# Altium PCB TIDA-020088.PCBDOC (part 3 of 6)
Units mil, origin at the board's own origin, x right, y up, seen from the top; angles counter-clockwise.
Board outline 7520.69 x 5119.11 mil, 6 copper layers (TOP, GND02, SIG03, SIG04, GND05, BOTTOM), stack 87.024 mil thick; 539 components, 269 nets, 1479 pads, 2085 vias.
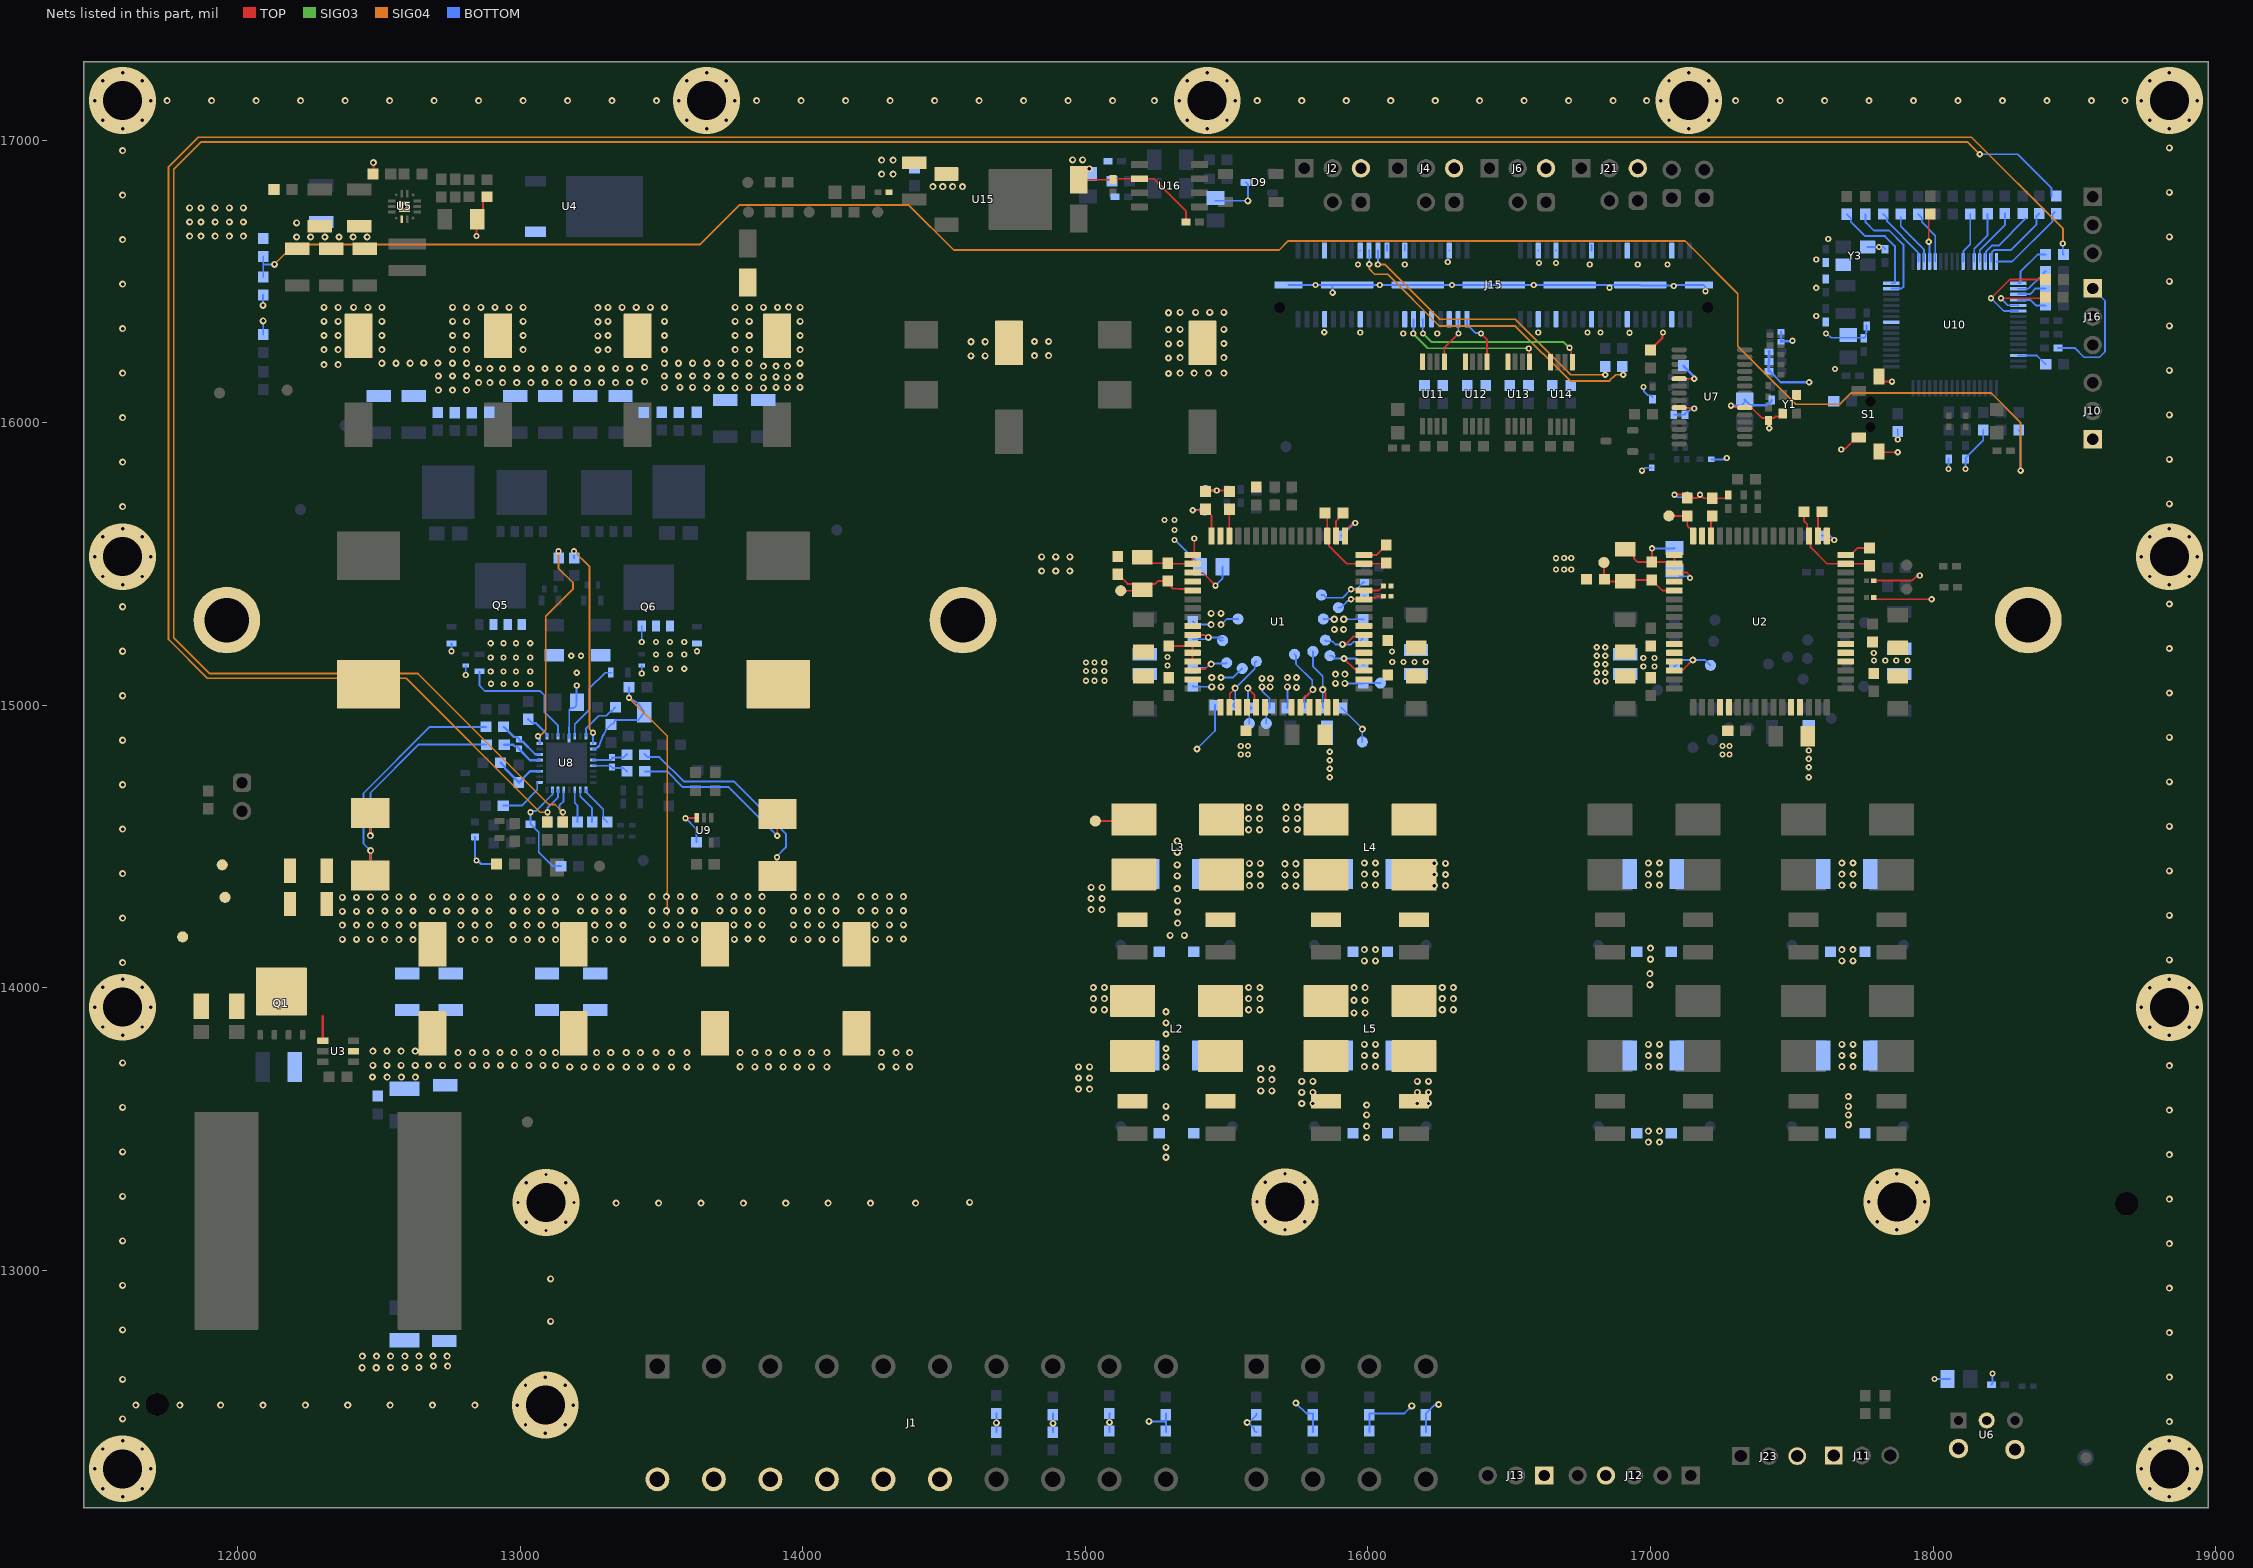
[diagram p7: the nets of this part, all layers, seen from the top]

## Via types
v1: diameter 25, hole 12, TOP to BOTTOM, tented both sides, 1621 vias
v2: diameter 22, hole 10, TOP to BOTTOM, tented both sides, 436 vias
v3: diameter 236.22, hole 137.8, TOP to BOTTOM, 15 vias
v4: diameter 19.68, hole 7.87, TOP to BOTTOM, tented both sides, 12 vias
v5: diameter 19.68, hole 7.87, TOP to BOTTOM, 1 vias

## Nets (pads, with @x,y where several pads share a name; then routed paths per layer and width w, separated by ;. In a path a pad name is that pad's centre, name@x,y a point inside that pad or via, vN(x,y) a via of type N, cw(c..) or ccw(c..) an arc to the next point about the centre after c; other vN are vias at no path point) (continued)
BIAS: C115.1 C116.1 C117.1 C118.1 C155.1 C156.1 C157.1 C158.1 C159.1 C160.1 C182.2 C183.1 D1.1 D2.1 L1.1 L6.1 L11.1 L13.1 L21.1 Q1.5 Q1.6 Q1.7 Q1.8 Q1.9@12154.41,13986.97 R62.1 R77.2 R78.1 R88.2 R89.2 R94.1 TP60.1 U3.4 U8.18 | length 2986.9
  TOP w6.5: R77.2@12469.31,14397.51 12470,14398.2 v1(12470,14485) ; v2(13908,14461.62) 13908,14396.76 R78.1@13910,14394.76
  TOP w8: 12300,13900 12300.87,13899.13 U3.4@12300.87,13812.4
  SIG04 w6.5: v2(13384.49,15026.46) 13520,14890.95 13520,14335.68 13519.44,14335.12 13519.44,14322.88 13520,14322.32 13519.44,14321.76 13519.44,14309.52 13520,14308.96 13520,14279.8 13519.44,14279.25 13519.44,14272.88 13520,14272.32 13520,14257.51
  BOTTOM w6.5: 12450,14400.42 12465,14415.42 ; v1(12470,14485) 12445,14510 12445,14688.33 12679.68,14923.01 R88.2@12878.05,14923.01 ; U8.18@13264.38,14844.84 U8.18@13257.65,14844.84 13265.46,14845.76 13273.95,14850.91 ; 13279.14,14857.14 13292.42,14891.84 ; 13293.17,14893.39 13306.23,14915.71 R94.1@13320.93,14931.4 13329.91,14934.97 13335.63,14947.08 13416.59,14947.08 C182.2@13438.18,14975.1 13416.59,15007.51 v2(13384.49,15026.46) 13384.49,15048.08 C183.1@13385.21,15062.78 ; R89.2@13439.99,14827.01 13450.78,14816.21 13492.12,14816.21 13578.33,14730 13755,14730 13940,14545 13940,14496.39 13908,14464.39 v2(13908,14461.62)
  BOTTOM w8: 12470,14450 v1(12470,14485) ; 13273.95,14850.91 ccw(c13267.49,14861.57) 13279.14,14857.14 ; 13292.42,14891.84 cw(c13302.23,14888.09) 13293.17,14893.39 ; 13908,14429.19 v2(13908,14461.62)
  other v1: 12520,14170 12570,14170 12620,14170 12790,14170 12840,14170 12890,14170 12975,14170 13025,14170 13075,14170 13125,14170 13265,14170 12370.31,14171.36 12420.31,14171.36 12470.31,14171.36 13313.42,14171.36 13363.42,14171.36 13467.52,14170.96 13517.52,14170.96 13567.52,14170.96 13617.52,14170.96 13757.52,14170.96 13967.52,14170.96 14017.52,14170.96 14067.52,14170.96 14117.52,14170.96 14257.52,14170.96 13805.94,14172.32 13855.94,14172.32 14305.94,14172.32 14355.94,14172.32 12370.31,14221.36 12420.31,14221.36 12470.31,14221.36 12520.31,14221.36 12570.31,14221.36 12620.31,14221.36 12789.68,14221.36 12839.68,14221.36 12889.68,14221.36 12974.05,14221.36 13024.05,14221.36 13074.05,14221.36 13124.05,14221.36 13263.42,14221.36 13313.42,14221.36 13363.42,14221.36 13466.57,14222.32 13516.57,14222.32 13566.57,14222.32 13616.57,14222.32 13755.94,14222.32 13805.94,14222.32 13855.94,14222.32 13966.57,14222.32 14016.57,14222.32 14066.57,14222.32 14116.57,14222.32 14255.94,14222.32 14305.94,14222.32 14355.94,14222.32 12370,14270 12420,14270 12470.31,14271.36 12520.31,14271.36 12570.31,14271.36 12620.31,14271.36 12689.68,14271.36 12739.68,14271.36 12789.68,14271.36 12839.68,14271.36 12889.68,14271.36 12974.05,14271.36 13024.05,14271.36 13074.05,14271.36 13124.05,14271.36 13213.42,14271.36 13263.42,14271.36 13313.42,14271.36 13363.42,14271.36 13466.57,14272.32 13516.57,14272.32 13566.57,14272.32 13616.57,14272.32 13705.94,14272.32 13755.94,14272.32 13805.94,14272.32 13855.94,14272.32 13966.57,14272.32 14016.57,14272.32 14066.57,14272.32 14116.57,14272.32 14205.94,14272.32 14255.94,14272.32 14305.94,14272.32 14355.94,14272.32 12370,14320 12420,14320 12470.31,14321.36 12520.31,14321.36 12570.31,14321.36 12620.31,14321.36 12689.68,14321.36 12739.68,14321.36 12789.68,14321.36 12839.68,14321.36 12889.68,14321.36 12974.05,14321.36 13024.05,14321.36 13074.05,14321.36 13124.05,14321.36 13213.42,14321.36 13263.42,14321.36 13313.42,14321.36 13363.42,14321.36 13466.57,14322.32 13516.57,14322.32 13566.57,14322.32 13616.57,14322.32 13705.94,14322.32 13755.94,14322.32 13805.94,14322.32 13855.94,14322.32 13966.57,14322.32 14016.57,14322.32 14066.57,14322.32 14116.57,14322.32 14205.94,14322.32 14255.94,14322.32 14305.94,14322.32 14355.94,14322.32 14845,15475 14895,15475 14945,15475 14845,15525 14895,15525 14945,15525 11829.5,16660 11870,16660 11920,16660 11970,16660 12020,16660 11829.5,16710 11870,16710 11920,16710 11970,16710 12020,16710 11829.5,16760 11870,16760 11920,16760 11970,16760 12020,16760 14278.8,16879.14 14319.3,16879.14 14278.8,16929.14 14319.3,16929.14
  other v2: 16665,15480.63 16694.37,15480.63 16719.37,15480.63 16665,15520 16694.37,15520.63 16719.37,15520.63
CAN_RX: R79.2 U10.6 | length 335.9
  TOP w6.5: v2(18205,16440) 18271.46,16506.46 R79.2@18398.5,16506.46
  BOTTOM w6.5: v2(18205,16440) 18250.01,16394.99 U10.6@18301.19,16394.99
CAN_STB: R71.2 U10.52 | length 171.6
  TOP w6.5: v2(17985,16640) 17985,16733.44 R71.2@17989.63,16738.08 R71.2@17990,16737.71
  BOTTOM w6.5: v2(17985,16640) 17987.29,16637.71 17987.29,16571.09 U10.52@17988.2,16570.19
CAN_TX: R70.2 U10.5 | length 230.7
  TOP w6.5: v2(18240,16440) 18393.26,16440 R70.2@18397.31,16444.05
  BOTTOM w6.5: v2(18240,16440) 18264.42,16415.58 18300.28,16415.58 U10.5@18301.19,16414.68
CFG0: R110.1 U8.27 | length 111.8
  BOTTOM w6.5: U8.27@13192.69,14694.33 13192.69,14653.94 13202.26,14644.37 R110.1@13202.26,14586.5
CFG1: R107.2 U8.26 | length 132
  BOTTOM w6.5: U8.26@13212.37,14701.14 13212.37,14677.63 13254.26,14635.74 R107.2@13254.26,14586.5
CFG2: R103.1 U8.25 | length 145.8
  BOTTOM w6.5: U8.25@13232.06,14701.14 13232.06,14692.94 13293.56,14631.44 13293.56,14600.2 R103.1@13307.26,14586.5
COMP: C191.1 C192.1 U8.3 | length 187.5
  BOTTOM w8: C192.1@12930.41,14796 12931.4,14796 12946.1,14781.3 12946.1,14775.71 C191.1@12995.11,14726.69 ; C191.1@12995.11,14725.71 C191.1@12995.11,14726.69 ; U8.3@13068.67,14766.1 13034.52,14766.1 C191.1@12995.11,14726.69
CSN1: C177.2 R87.1 U8.5 | length 149.2
  BOTTOM w8: R87.1@12943.17,14860.31 12974.86,14860.31 12981.5,14853.66 12987.84,14853.66 12995.11,14846.4 C177.2@12995.11,14845.55 12995.11,14844.71 13034.35,14805.47 U8.5@13068.67,14805.47
CSN2: C178.2 R90.1 U8.21 | length 128.6
  BOTTOM w6.5: U8.21@13257.65,14785.79 13313.5,14785.79 13314.68,14784.61 13319.36,14784.61 13325.63,14778.34 13325.63,14777.5 13365.16,14777.5 R90.1@13377.27,14765.39
CSP1: C177.1 R88.1 U8.6 | length 169.1
  BOTTOM w8: R88.1@12941.04,14923.01 12942.03,14923.01 12977.63,14887.41 12987.84,14887.41 12995.11,14880.14 C177.1@12995.11,14879.3 12995.11,14878.45 13002.38,14871.18 13007.71,14871.18 13052.93,14825.97 13067.86,14825.97 U8.6@13068.67,14825.16
CSP2: C178.1 R89.1 U8.20 | length 128.1
  BOTTOM w6.5: U8.20@13257.65,14805.47 13257.73,14805.55 13319.94,14805.55 C178.1@13325.63,14811.24 ; C178.1@13324.43,14814.58 13364.56,14814.58 R89.1@13376.99,14827.01
DLY: C194.1 U8.1 | length 171.1
  BOTTOM w6.5: C194.1@12939.61,14644.37 13004.37,14644.37 13060.11,14700.11 13060.11,14725.06 13061.78,14726.73 U8.1@13061.94,14726.73
EN2: R97.2 R101.1 R145.2 U8.30 | length 10407.7
  TOP w6.5: R101.1@13095.63,14586.5 13096.39,14587.26 v2(13096.39,14620.98)
  SIG04 w6.5: v2(13096.39,14620.98) 13069.67,14620.98 12595.66,15095 11892.37,15095 11755,15232.37 11755,16905 11860,17010 18136.11,17010 18460,16686.11 18460,16635 v2(18458.94,16633.94)
  BOTTOM w6.5: R97.2@13095.63,14586.5 13096.39,14587.26 v2(13096.39,14620.98) 13096.72,14621.31 13096.72,14637.42 13133.63,14674.33 U8.30@13133.63,14701.14 ; v2(18458.94,16633.94) 18458.94,16597.55 R145.2@18461.5,16595
GND: C1.1 C2.2 C3.1 C4.1 C6.2 C7.2 C8.2 C9.1 C10.2 C11.2 C13.2 C14.2 C15.2 C16.2 C17.2 C18.2 C20.2 C21.2 C23.2 C24.2 C25.2 C26.2 C27.2 C28.2 C31.2 C32.2 C33.2 C34.2 C35.2 C36.2 C39.2 C40.2 C41.2 C42.2 C43.2 C44.2 C47.2 C48.2 C49.2 C50.2 C51.2 C52.2 C53.1 C54.2 C55.1 C56.1 C58.2 C59.2 C60.2 C61.1 C62.2 C63.2 C65.2 C66.2 C67.2 C68.2 C69.2 C70.2 C72.2 C73.2 C75.2 C76.2 C77.2 C78.2 C79.2 C80.2 C83.2 C84.2 C85.2 C86.2 C87.2 C88.2 C91.2 C92.2 C93.2 C94.2 C95.2 C96.2 C99.2 C100.2 C101.2 C102.2 C103.2 C104.2 C106.2 C107.2 C108.2 C109.2 C110.2 C111.2 C112.2 C113.2 C114.2 C115.2 C116.2 C117.2 C118.2 C120.2 C121.2 C122.2 C123.2 C124.2 C125.2 C126.2 C127.2 C128.2 C129.2 C130.2 C131.2 C132.2 C133.2 C134.1 C135.1 C136.2 C137.2 C138.2 C139.2 C140.1 C141.2 C142.2 C143.1 C144.2 C145.2 C146.2 C147.2 C148.2 C149.2 C150.2 C151.2 C152.2 C153.2 C154.1 C155.2 C156.2 C157.2 C158.2 C159.2 C160.2 C161.2 C162.2 C163.2 C164.2 C165.2 C166.2 C167.2 C168.2 C169.2 C170.2 C171.2 C172.2 C173.2 C174.2 C187.1 C188.1 C189.2 C193.2 C196.1 C197.1 C198.1 C199.1 C200.2 C201.2 C202.1 C203.2 C204.2 C206.1 C207.1 C208.1 C209.1 C210.1 C211.1 C212.1 C213.1 C214.1 C215.1 C216.2 C217.2 C218.2 C219.2 C220.2 C221.2 C222.2 C223.2 C224.2 C225.2 D9.3 J1.2 J1.4 J1.6 J1.8 J1.10 J1.12 J2.3 J4.3 J6.3 J10.1 J11.1 J12.4 J13.1 J15.7 J15.8 J15.15 J15.16 J15.22 J15.25 J15.26 J15.31 J15.35 J15.36 J15.45 J15.46 J15.49 J15.50 J15.57 J15.58 J15.65 J15.66 J15.75 J15.76 J15.P1 J15.P2 J16.1 J21.3 J23.3 NT1.2 pad.1@11961.37,15301.37 pad.1@14566.37,15301.37 pad.1@18336.64,15301.37 Q5.1 Q5.2 Q5.3 Q6.1 Q6.2 Q6.3 R19.2 R34.2 R36.2 R39.1 R41.1 R51.2 R54.2 R55.2 R57.1 R58.2 R63.2 R86.1 R91.1 R92.1 R93.1 R112.1 R121.2 R126.1 RT3.1 RT4.1 S1.1 S1.2 S1.3 TP2.1 TP30.1 TP76.1 TP77.1 U1.1 U1.15 U1.17 U1.18 U1.20 U1.27 U1.28 U1.29 U1.36 U1.37 U1.44 U1.45 U1.52 U1.53 U1.54 U2.1 U2.15 U2.17 U2.18 U2.20 U2.27 U2.28 U2.29 U2.36 U2.37 U2.44 U2.45 U2.52 U2.53 U2.54 U3.2 U4.1 U5.6 U5.15 U6.2 U6.4 U6.5 U7.6 U7.19 U7.23 U8.13 U9.3 U10.41 U11.4 U12.4 U13.4 U14.4 U15.1 U16.2 Y1.2 Y1.4 Y3.2 Y3.4 | length 8494
  TOP w6.5: R41.1@12478.5,16880 12480,16881.5 v1(12480,16920) ; v2(12845,16660) 12845,16717.91 C122.2@12847.09,16720 12867.68,16740.59 12867.68,16786.3 12881.38,16800 R36.2@12881.5,16800 12882.48,16800 12896.18,16786.3 R36.2@12896.18,16785.31 ; v2(13585,14600) 13585.91,14600.91 13623.5,14600.91 U9.3@13624.41,14601.81 ; C114.2@14976.56,16859.82 15097.31,16859.82 C172.2@15097.35,16859.86 15100.84,16863.35 U16.2@15191.58,16863.35 15241.65,16863.35 15356.38,16748.62 C171.2@15356.38,16710 ; C13.2@15200.63,15522.71 15221.2,15502.14 C14.2@15290.63,15502.14 15292.41,15500.35 U1.18@15379.37,15500.35 U1.17@15379.37,15531.85 15385,15537.48 v2(15385,15590) ; C3.1@15295.63,15209.14 15352.92,15209.14 15360.67,15216.89 U1.27@15379.37,15216.89 U1.28@15379.37,15185.39 U1.29@15379.37,15153.9 ; C1.1@15425,15756.5 15428.5,15760 v2(15465,15760) 15506.5,15760 C9.1@15510,15756.5 ; U1.1@15918.74,15598.78 15918.74,15617.48 15943.96,15642.7 15952.7,15642.7 v2(15955,15645) ; C65.2@16923.47,15565.56 C65.2@16910,15552.09 16920.83,15552.09 16941.42,15531.5 16941.42,15520.67 16955.59,15506.5 C66.2@17005,15506.5 17059.53,15506.5 17065.67,15500.35 U2.18@17084.37,15500.35 U2.17@17084.37,15531.85 ; v2(17085,15745) 17117.99,15745 C53.1@17130,15732.99 17162.99,15732.99 v2(17175,15745) 17187.63,15732.37 C61.1@17218.97,15732.37 17263.75,15732.37 17264.25,15732.87 17268.19,15732.87 17275,15739.68 R34.2@17275,15743.62 ; U7.23@17101.14,16052.98 17102.61,16051.51 17153.49,16051.51 v2(17155,16050) ; U7.19@17101.14,16155.35 17154.65,16155.35 v2(17155,16155) ; v2(17285,16060) 17288.25,16060 17293.79,16054.46 U7.6@17333.42,16054.46 ; U7.6@17333.42,16052.98 17354.21,16052.98 17358.07,16049.13 17360.87,16049.13 17393.53,16016.47 17437.76,16016.47 17443.33,16022.03 17457.82,16022.03 Y1.2@17467.91,16032.13 ; U2.1@17623.74,15598.78 17623.74,15592.58 17631.32,15585 v2(17650,15585) ; v2(17675,15905) 17677.3,15907.3 17689.54,15907.3 17729.57,15947.32 S1.3@17737.44,15947.32 ; C72.2@17790,15380.94 17790.79,15380.94 17796.72,15375 v2(17995,15375) ; C73.2@17790,15440 17791.32,15441.32 17926.32,15441.32 17941.7,15456.7 17950.65,15456.7 v2(17952.95,15459) ; S1.1@17808.31,15897.13 17810.43,15895 v2(17875,15895) ; S1.2@17808.31,16162.87 17808.31,16159.69 17822.99,16145 v2(17855,16145)
  TOP w8: C137.2@17000,16256.5 17000,16257.48 17041.07,16298.55 17041.07,16315.92 v2(17043.75,16318.6) ; C66.2@17005,15506.5 v2(17005,15555) ; C128.2@17417.28,16007.75 17418.64,16006.39 17418.64,15981.36 v2(17420,15980)
  BOTTOM w6.5: v1(12089.18,16415.09) 12089.18,16451.18 R63.2@12090,16452.01 ; R51.2@12090,16311.5 v1(12090,16360) ; v2(12756.5,15191) RT3.1@12756.5,15218 ; v2(12806.83,15107.23) R92.1@12806.83,15140 ; NT1.2@13172.59,14882.69 13172.59,14922.4 13173.11,14922.4 13173.11,14983.55 13178.97,14989.41 13189.25,14989.41 13198.03,14998.19 13198.03,15010 13199.02,15010.98 13199.02,15069.02 v2(13200,15070) ; v2(13430,15112) R93.1@13430,15140 ; v2(13430,15223.86) Q6.3@13430,15279.96 ; v2(13585,14600) 13623.5,14561.5 C193.2@13623.5,14515 ; C27.2@14685,12426.57 v1(14685,12460) C28.2@14685,12493.43 ; C35.2@14885,12426.57 14885.4,12426.98 14885.4,12493.02 C36.2@14885,12493.43 ; C43.2@15085,12426.57 15085.07,12426.64 15085.07,12493.36 C44.2@15085,12493.43 ; v1(15225,12465) 15280,12465 15285,12460 ; C51.2@15285,12426.57 15285,12460 ; C52.2@15285,12493.43 15285,12460 ; v2(15315,15585) 15316.5,15585 15405,15496.5 C8.2@15405,15490 ; TP2.1@15425,15759.45 15425.28,15759.72 15464.72,15759.72 v2(15465,15760) ; C143.1@15460,16785.51 15460.26,16785.26 15574.74,16785.26 v1(15575,16785) 15575,16843.26 15568.26,16850 D9.3@15567.76,16850 ; C79.2@15605,12426.57 15604.02,12426.57 15596.22,12434.37 15596.22,12441.26 15576.24,12461.24 v1(15572.12,12461.24) 15577.99,12467.1 15584.58,12467.1 15605,12487.52 C80.2@15605,12493.43 ; J15.P1@15718.81,16487.46 v2(15814,16487.46) J15.P1@15867.4,16487.46 ; v1(15745,12530) 15781.57,12493.43 15805,12493.43 C87.2@15805,12426.57 ; v2(15875,16460) 15875,16479.86 J15.P1@15867.4,16487.46 ; C4.1@15906.5,15600 15907.48,15600 15952.48,15645 v2(15955,15645) ; C95.2@16005,12426.57 16005,12493.43 16129.37,12493.43 16155,12519.06 v1(16155,12520) ; J15.22@16067.24,16608.92 J15.22@16067.24,16628.4 ; J15.26@16130.23,16608.92 J15.26@16130.23,16628.4 ; C103.2@16205,12426.57 16205,12493.43 16205.98,12493.43 16234.69,12522.13 16247.13,12522.13 v1(16250,12525) ; J15.58@16791.65,16608.92 J15.58@16791.65,16628.4 ; v2(16855.3,16477.02) v2@16855.3,16487.46 ; v2(16970,15830) 16971.09,15830 16981.4,15840.32 R57.1@17004.37,15840.32 ; v2(16975,16126.06) 16977.3,16123.76 16977.3,16109.34 16990.02,16096.61 17001.01,16096.61 17007.28,16090.34 C136.2@17007.28,16089.5 ; v2(17005,15555) 17083.27,15555 C60.2@17084.37,15556.1 ; C134.1@17082.28,16027.75 C135.1@17122.28,16027.75 17122.28,16031.69 17129.09,16038.5 17133.03,16038.5 17142.24,16047.7 17152.7,16047.7 v2(17155,16050) ; v2(17082.53,16483.79) 17080.69,16485.62 16965.53,16485.62 J15.P2@16963.69,16487.46 v2@16855.3,16487.46 ; v2@17082.53,16487.46 17187.4,16487.46 17195,16479.86 v2(17195,16465) ; v2(17085,15745) 17087.35,15745 17096.4,15735.94 TP30.1@17130,15735.94 ; R54.2@17214.69,15870 17261.75,15870 17266.75,15875 v2(17270,15875) ; v2(17285,16060) 17320.81,16060 C133.2@17333.7,16072.89 ; C56.1@17606.5,15600 17635,15600 v2(17650,15585) ; v2(17620.77,16315.47) 17624.02,16315.47 17638.98,16300.51 17753.11,16300.51 C200.2@17755,16298.62 17761.81,16305.43 17761.81,16317.28 17765,16320.47 R121.2@17765,16344.82 ; Y3.4@17768.31,16621.5 17823.19,16621.5 17830,16614.69 C197.1@17830,16613.62 ; v2(17875,15940.29) C201.2@17875,15976.38 ; v2(18005,12615) C126.2@18060,12615 ; v2(18055,15836.22) C206.1@18055,15871.38 ; v2(18115,15836.22) 18115,15860.63 18119.37,15865 18120,15865 18115,15870 C207.1@18115,15871.38 18115,15875.32 18177.66,15937.97 C140.1@18177.66,15973.39 ; C127.2@18206.38,12595 18210,12598.62 v2(18210,12635) ; R126.1@18442.57,16264.75 R126.1@18442.05,16264.22 18501.55,16264.22 18534.26,16231.52 18589.14,16231.52 18608.48,16250.86 18608.48,16431.52 J16.1@18565,16475 ; J15.P1@15867.4,16487.46 v2(16041.46,16487.46) J15.P1@16176.29,16487.46 v2(16297.04,16487.46) J15.P1@16383.77,16487.46 J15.P2@16506.21,16487.46 v2(16586.54,16487.46) J15.P2@16713.69,16487.46 v2@16855.3,16487.46
  BOTTOM w8: C187.1@12840,14533.43 12840,14458.79 12845,14453.79 v2(12845,14450) 12848.79,14450 12861.02,14437.77 C188.1@12922.91,14437.77 ; C138.2@17116.69,16201.76 17116.69,16200.77 17152.32,16165.14 17152.32,16157.68 v2(17155,16155) ; C133.2@17333.7,16081.37 17353.38,16061.69 17410.18,16061.69 17416.86,16068.37 17420.8,16068.37 17428.61,16076.18 C129.2@17428.61,16080.12 ; C132.2@17418.66,16251.37 17420.63,16253.34 17420.63,16218.34 C130.2@17418.66,16216.37 C131.2@17418.66,16181.37 17422.6,16181.37 17461.06,16142.9 v2(17561.45,16142.9) ; R58.2@17461.97,16321.37 R55.2@17461.97,16286.37 17463.78,16288.18 17501.19,16288.18 v2(17503,16290)
  other v1: 11592.36,12198.06 18836.45,12198.06 11522.28,12227.09 11662.43,12227.09 18766.38,12227.09 18906.53,12227.09 11493.26,12297.17 11691.46,12297.17 18737.35,12297.17 18935.55,12297.17 11522.28,12367.24 11662.43,12367.24 18766.38,12367.24 18906.53,12367.24 11592.36,12396.27 18836.45,12396.27 13088.42,12423.65 13018.34,12452.68 13158.5,12452.68 14885.4,12457.92 15085.07,12461.87 18836.45,12464.49 11592.36,12474.33 11639.32,12522.76 11794.9,12522.81 11939.32,12522.76 12089.32,12522.76 12239.32,12522.76 12389.32,12522.76 12539.32,12522.76 12689.32,12522.76 12839.32,12522.76 12989.32,12522.76 13187.52,12522.76 13018.34,12592.83 13158.5,12592.83 11592.36,12613.81 13088.42,12621.86 18836.45,12621.97 12440,12655 12490,12655 12541.09,12655.9 12591.09,12655.9 12641.09,12655.9 12692.67,12660.76 12742.67,12660.76 12441.09,12695.9 12491.09,12695.9 12541.09,12695.9 12591.09,12695.9 12641.09,12695.9 12691.09,12695.9 12741.09,12695.9 18836.45,12779.45 11592.36,12789.29 13107.24,12819.32 18836.45,12936.93 11592.36,12946.77 13107.24,12969.32 18836.45,13094.41 11592.36,13104.25 13090.81,13140.56 15706.53,13142.79 17871.89,13142.95 13020.73,13169.58 13160.89,13169.58 15636.46,13171.81 15776.61,13171.81 17801.81,13171.97 17941.96,13171.97 13339.32,13237.76 13489.32,13237.76 13639.32,13237.76 13789.32,13237.76 13939.32,13237.76 14089.32,13237.76 14239.32,13237.76 14399.32,13237.76 12991.71,13239.66 13189.91,13239.66 14590,13240 15607.43,13241.89 15805.63,13241.89 17772.78,13242.05 17970.99,13242.05 18836.45,13251.89 11592.36,13261.73 13020.73,13309.74 13160.89,13309.74 15636.46,13311.97 15776.61,13311.97 17801.81,13312.12 17941.96,13312.12 13090.81,13338.76 15706.53,13340.99 17871.89,13341.15 15285,13400 18836.45,13409.37 11592.36,13419.21 15285,13435 16992.28,13453.2 17031.65,13453.2 15995,13470 16992.28,13492.57 17031.65,13492.57 15995,13510 17700,13515 15285,13540 15995,13550 17700,13550 18836.45,13566.85 11592.36,13576.69 15285,13580 17700,13580 15995,13585 17700,13615 12476.77,13683.88 12528.73,13683.58 12578.73,13683.58 12628.73,13683.58 13175,13720 13225,13720 13270,13720 13320,13720 13375,13720 13425,13720 13480,13720 13535,13720 13590,13720 13778.04,13720.3 13830,13720 13878.04,13720.3 13930,13720 13980,13720 14030,13720 14085,13720 14278.04,13720.3 14330,13720 14378.04,13720.3 15285,13720 15987.28,13720.81 16026.65,13720.81 16992.28,13720.81 17031.65,13720.81 17677.28,13720.81 17716.65,13720.81 18836.45,13724.33 12478.04,13725.3 12528.04,13725.3 12578.04,13725.3 12628.04,13725.3 12675,13725 12725,13725 12780,13725 12830,13725 12880,13725 12930,13725 12980,13725 13030,13725 13080,13725 13125,13725 11592.36,13734.17 15285,13755 15987.28,13760.18 16026.65,13760.18 16992.28,13760.18 17031.65,13760.18 17677.28,13760.18 17716.65,13760.18 12780,13770 12830,13770 12878.04,13770.3 12928.04,13770.3 12978.04,13770.3 13030,13770 13080,13770 13125,13770 13270,13770 13320,13770 13375,13770 13425,13770 13480,13770 13535,13770 13590,13770 13778.04,13770.3 13830,13770 13878.04,13770.3 13930,13770 13980,13770 14030,13770 14085,13770 14278.04,13770.3 14330,13770 14378.04,13770.3 12478.04,13775.3 12528.04,13775.3 12578.04,13775.3 12628.04,13775.3 15285,13785 15987.28,13799.55 16026.65,13799.55 16992.28,13799.55 17031.65,13799.55 17677.28,13799.55 17716.65,13799.55 18836.45,13831.24 11592.36,13831.92 15285,13836.26 18766.38,13860.26 18906.53,13860.26 11522.28,13860.95 11662.44,13860.95 15285,13875.63 15285,13915 18737.36,13930.34 18935.56,13930.34 11493.26,13931.02 11691.46,13931.02 18766.38,14000.41 18906.53,14000.41 11522.28,14001.1 11662.44,14001.1 16997.72,14010.43 18836.45,14029.44 11592.36,14030.13 16997.72,14049.8 11592.36,14088.5 15987.28,14095.2 16026.65,14095.2 17677.28,14095.2 17716.65,14095.2 18836.45,14098.35 17000,14100.63 15987.28,14134.57 16026.65,14134.57 17677.28,14134.57 17716.65,14134.57 17000,14140 15300,14185 15350,14185 15326.65,14228.44 11592.36,14245.98 18836.45,14255.83 15326.65,14267.81 15326.65,14307.18 15325,14350.63 15987.28,14362.81 16026.65,14362.81 16992.28,14362.81 17031.65,14362.81 17677.28,14362.81 17716.65,14362.81 15325,14395.63 15987.28,14402.18 16026.65,14402.18 16992.28,14402.18 17031.65,14402.18 17677.28,14402.18 17716.65,14402.18 11592.36,14403.46 18836.45,14413.31 15325,14435 15987.28,14441.55 16026.65,14441.55 16992.28,14441.55 17031.65,14441.55 17677.28,14441.55 17716.65,14441.55 15325,14479.37 15325,14520 11592.36,14560.95 18836.45,14570.79 11592.36,14718.43 18836.45,14728.27 11592.36,14875.91 18836.45,14885.75 11592.36,15033.39 18836.45,15043.23 11592.36,15190.87 18836.45,15200.71 11592.36,15348.35 18836.45,15358.19 11592.36,15426.41 18836.45,15426.41 11522.28,15455.44 11662.43,15455.44 18766.38,15455.44 18906.53,15455.44 11493.26,15525.51 11691.46,15525.51 18737.35,15525.51 18935.55,15525.51 11522.28,15595.59 11662.43,15595.59 18766.38,15595.59 18906.53,15595.59 11592.36,15624.61 18836.45,15624.61 11592.36,15702.68 18836.45,15712.52 11592.36,15860.16 18836.45,15870 11592.36,16017.64 18836.45,16027.48 12710,16115 12760,16115 12810,16115 13660.22,16123.19 13710.22,16123.19 13760.22,16123.19 13860.22,16123.19 13510,16125 13565,16125 13610,16125 13810,16125 13905,16125 13945,16125 13990,16125 12852.32,16141.39 12892.32,16141.39 12937.32,16141.39 12987.32,16141.39 13037.32,16141.39 13087.32,16141.39 13137.32,16141.39 13187.32,16141.39 13237.32,16141.39 13287.32,16141.39 13337.32,16141.39 13387.32,16141.39 13440,16145 13860,16160 13945,16160 13904.78,16161.81 12710,16165 12760,16165 12810,16165 13510,16165 13560,16165 13610,16165 13660,16165 13710,16165 13760,16165 13810,16165 13990,16165 15294,16173.8 11592.36,16175.12 15335,16175 15385,16175 15435,16175 15490,16175 18836.45,16184.96 12852.32,16191.39 12892.32,16191.39 12937.32,16191.39 12987.32,16191.39 13037.32,16191.39 13087.32,16191.39 13137.32,16191.39 13187.32,16191.39 13237.32,16191.39 13287.32,16191.39 13337.32,16191.39 13387.32,16191.39 13440,16195 13860,16200 13905,16200 13945,16200 12305,16205 12355,16205 12510,16210 12560,16210 12610,16210 12760,16210 12810,16210 13510,16210 13560,16210 13610,16210 13660,16210 13710,16210 13760,16210 13810,16210 13990,16210 12658.25,16210.94 12708.25,16210.94 15294,16228.8 15335,16230 15490,16230 14595.2,16236.24 14645.2,16236.24 14819.72,16237.12 14869.72,16237.12 13274.15,16257.07 12305.22,16258.19 12355.22,16258.19 12510.22,16258.19 12760.22,16258.19 12810.22,16258.19 13010.22,16258.19 13310.22,16258.19 13510.22,16258.19 13760.22,16258.19 13810.22,16258.19 13990.22,16258.19 15294,16278.8 15335,16280 15490,16280 14595.2,16286.24 14645.2,16286.24 14819.72,16287.12 14869.72,16287.12 13274.15,16307.07 12305.22,16308.19 12355.22,16308.19 12510.22,16308.19 12760.22,16308.19 12810.22,16308.19 13010.22,16308.19 13310.22,16308.19 13510.22,16308.19 13760.22,16308.19 13810.22,16308.19 13990.22,16308.19 15294,16328.8 15335,16330 15490,16330 11592.36,16332.6 18836.45,16342.44 13274.15,16357.07 12305.22,16358.19 12355.22,16358.19 12510.22,16358.19 12760.22,16358.19 12810.22,16358.19 13010.22,16358.19 13310.22,16358.19 13510.22,16358.19 13760.22,16358.19 13810.22,16358.19 13990.22,16358.19 15294,16388.8 15335,16390 15390,16390 15440,16390 15490,16390 13274.15,16407.07 12305.22,16408.19 12355.22,16408.19 12410.22,16408.19 12460.22,16408.19 12510.22,16408.19 12760.22,16408.19 12810.22,16408.19 12860.22,16408.19 12910.22,16408.19 12960.22,16408.19 13010.22,16408.19 13310.22,16408.19 13360.22,16408.19 13410.22,16408.19 13460.22,16408.19 13510.22,16408.19 13760.22,16408.19 13810.22,16408.19 13860.22,16408.19 13910.22,16408.19 13990.22,16408.19 13949.63,16408.63 11592.36,16490.08 18836.45,16499.92 11592.36,16647.56 12208.07,16657.12 12258.07,16657.12 12308.07,16657.12 12358.07,16657.12 12408.07,16657.12 12458.07,16657.12 18836.45,16657.4 12208.07,16707.12 11592.36,16805.04 18836.45,16814.88 14460,16835 14495,16835 14530,16835 14565,16835 15014.04,16898.14 14955,16930 14990,16930 11592.36,16962.52 18836.45,16972.36 11592.36,17040.58 13659.29,17040.58 15430.94,17040.58 17135.67,17040.58 18836.45,17040.58 11522.28,17069.61 11662.43,17069.61 13589.21,17069.61 13729.36,17069.61 15360.86,17069.61 15501.02,17069.61 17065.59,17069.61 17205.74,17069.61 18766.38,17069.61 18906.53,17069.61 11493.26,17139.69 11691.46,17139.69 11749.84,17139.69 11907.32,17139.69 12064.8,17139.69 12222.28,17139.69 12379.76,17139.69 12537.24,17139.69 12694.72,17139.69 12852.2,17139.69 13009.68,17139.69 13167.16,17139.69 13324.64,17139.69 13482.12,17139.69 13560.18,17139.69 13758.39,17139.69 13836.45,17139.69 13993.93,17139.69 14151.41,17139.69 14308.89,17139.69 14466.37,17139.69 14623.85,17139.69 14781.33,17139.69 14938.81,17139.69 15096.3,17139.69 15243.93,17139.69 15331.84,17139.69 15530.04,17139.69 15608.11,17139.69 15765.59,17139.69 15923.07,17139.69 16080.55,17139.69 16238.03,17139.69 16395.51,17139.69 16552.99,17139.69 16710.47,17139.69 16867.95,17139.69 16986.06,17139.69 17036.56,17139.69 17234.77,17139.69 17301.02,17139.69 17458.5,17139.69 17615.98,17139.69 17773.46,17139.69 17930.94,17139.69 18088.42,17139.69 18245.9,17139.69 18403.38,17139.69 18560.86,17139.69 18678.97,17139.69 18737.35,17139.69 18935.55,17139.69 11522.28,17209.76 11662.43,17209.76 13589.21,17209.76 13729.36,17209.76 15360.86,17209.76 15501.02,17209.76 17065.59,17209.76 17205.74,17209.76 18766.38,17209.76 11592.36,17238.79 13659.29,17238.79 15430.94,17238.79 17135.67,17238.79 18836.45,17238.79
  other v2: 15865,14745 17560,14745 15865,14775 17560,14780 15865,14805 17560,14810 15550,14825 15575,14825 17255,14825 17280,14825 15865,14835 17560,14840 15550,14855 15575,14855 17255,14855 17280,14855 12940,15074.49 12985,15074.49 13035,15074.49 12896.41,15075.9 16810,15085 16840,15085 15001.7,15086.39 15031.7,15086.39 15067.62,15086.66 13200,15115 16810,15115 16840,15115 12895,15118.86 12940,15118.86 12985,15118.86 13035,15118.86 15001.81,15120.8 15031.81,15120.8 15066.81,15120.8 13480,15128.86 13530,15128.86 13580,15128.86 16974.67,15137.22 17014.04,15137.22 15290,15140 16810,15145 16840,15145 15001.81,15150.8 15031.81,15150.8 15066.81,15150.8 16086.22,15152.8 16125.59,15152.8 16164.96,15152.8 16204.33,15152.8 17791.22,15157.8 17830.59,15157.8 17869.96,15157.8 17909.33,15157.8 16974.67,15167.22 17014.04,15167.22 12895,15168.86 12940,15168.86 12985,15168.86 13035,15168.86 15290,15170 13180,15175 13215,15175 16810,15175 16840,15175 13480,15178.86 13530,15178.86 13580,15178.86 17790,15185 16085,15190 13625,15191 16810,15205 16840,15205 12895,15218.86 12940,15218.86 12985,15218.86 13035,15218.86 13480,15223.86 13530,15223.86 13580,15223.86 15315,15620 15280,15655 15315,15655 17652.78,16190 16125,16315 16245,16315 15972.74,16318.46 16602.67,16318.46 16777,16318.46 16823.14,16318.46 16925.2,16318.26 15845,16320 17586.5,16377 17586.5,16477 15965,16560 16130,16560 16785,16560 16955,16560 17060,16560 16605,16565 16665,16565 16282.19,16568 17586.5,16577 17808.35,16621.5 17629,16650 12590.44,16765.44
  other v3: 11592.36,12297.17 18836.45,12297.17 13088.42,12522.76 13090.81,13239.66 15706.53,13241.89 17871.89,13242.05 18836.45,13930.34 11592.36,13931.02 11592.36,15525.51 18836.45,15525.51 11592.36,17139.69 13659.29,17139.69 15430.94,17139.69 17135.67,17139.69 18836.45,17139.69
  other v5: 12590,16765
GPIO_MCU_0: R125.1 U10.47 | length 390.5
  BOTTOM w6.5: R125.1@17760,16737.4 17761.43,16735.97 17761.43,16708.57 17790,16680 17845,16680 17895,16630 17895,16480.5 17889.14,16474.64 17853.28,16474.64 U10.47@17852.37,16473.73
GPIO_MCU_1: R130.1 U10.48 | length 367.4
  BOTTOM w6.5: R130.1@17695,16737.4 17708.6,16723.8 17708.6,16711.4 17760,16660 17829.75,16660 17865,16624.75 17865,16494.32 17864.09,16493.42 U10.48@17852.37,16493.42
GPIO_MCU_2: R132.1 U10.50 | length 219.6
  BOTTOM w6.5: R132.1@17823.6,16737.9 17837.24,16724.26 17837.24,16711.94 17946.05,16603.13 17946.05,16600.19 17947.92,16598.32 17947.92,16571.09 U10.50@17948.83,16570.19
GPIO_MCU_3: R133.1 U10.51 | length 192.6
  BOTTOM w6.5: R133.1@17885.58,16728.42 17885.58,16694.42 17968.51,16611.49 U10.51@17968.51,16570.19
GPIO_MCU_5: R137.1 U10.53 | length 192.2
  BOTTOM w6.5: R137.1@17947.38,16737.34 17959.82,16724.9 17959.82,16710.18 18007.88,16662.12 U10.53@18007.88,16570.19
GPIO_MCU_6: R138.1 U10.58 | length 178.6
  BOTTOM w6.5: U10.58@18106.31,16570.19 18107.21,16571.09 18107.21,16607.21 18131.58,16631.58 R138.1@18131.58,16738.35
GPIO_MCU_8: R140.1 U10.60 | length 188.6
  BOTTOM w6.5: U10.60@18145.68,16570.19 18145.68,16615.68 18192.88,16662.88 R140.1@18192.88,16739.19
GPIO_MCU_9: R141.1 U10.61 | length 206.2
  BOTTOM w6.5: U10.61@18165.36,16570.19 18165.36,16610.36 18254.16,16699.16 R141.1@18254.16,16739.63
GPIO_MCU_10: R142.1 U10.62 | length 224.2
  BOTTOM w6.5: U10.62@18185.05,16570.19 18185.95,16571.09 18185.95,16598.32 18187.83,16600.19 18187.83,16606.07 18208.47,16626.72 18231.72,16626.72 R142.1@18326.98,16721.98
GPIO_MCU_11: R143.1 U10.63 | length 275.6
  BOTTOM w6.5: U10.63@18204.73,16570.19 18205.64,16571.09 18205.64,16598.32 18207.51,16600.19 18207.51,16603.13 18215.1,16610.72 18275.72,16610.72 18365.8,16700.8 18365.8,16730.08 R143.1@18375.34,16739.62
GPIO_MCU_12: R144.1 U10.64 | length 292.9
  BOTTOM w6.5: U10.64@18224.42,16570.19 18280.19,16570.19 18422.91,16712.91 18422.91,16738.14 R144.1@18430,16745.23
GPIO_MCU_13: R145.1 U10.1 | length 163.2
  BOTTOM w6.5: U10.1@18301.19,16493.42 18309.09,16493.42 18310,16494.32 18310,16535 18369.68,16594.68 18398.18,16594.68 R145.1@18398.5,16595
GPIO_MCU_14: R146.1 U10.2 | length 123.3
  BOTTOM w6.5: U10.2@18301.19,16473.73 18337.24,16473.73 18383.82,16520.31 18383.82,16521.3 18397.52,16535 R146.1@18398.5,16535
GPIO_MCU_15: R147.1 U10.3 | length 106
  BOTTOM w6.5: U10.3@18301.19,16454.05 18302.09,16454.95 18343.77,16454.95 18363.82,16475 R147.1@18398.5,16475
GPIO_MCU_16: R150.1 U10.4 | length 105.3
  BOTTOM w6.5: U10.4@18301.19,16434.36 18302.09,16433.46 18345.36,16433.46 18363.82,16415 R150.1@18398.5,16415
GPIO_MCU_17: R151.1 U10.14 | length 110.2
  BOTTOM w6.5: U10.14@18301.19,16237.51 18367.67,16237.51 18397.91,16207.27 R151.1@18398.9,16207.27
HB1: C179.2 U8.9 | length 94.7
  BOTTOM w8: C179.2@13028.49,14950.2 13041.88,14936.81 13054.46,14936.81 13075.05,14916.22 13094.26,14897.01 U8.9@13094.26,14890.12
HB2: C180.1 U8.16 | length 163
  BOTTOM w6.5: U8.16@13232.06,14890.12 13232.14,14890.2 13232.14,14905.42 ; 13232.06,14905.42 13232.06,14917.06 13277.43,14962.43 13297.31,14962.43 13297.46,14962.58 13303.33,14962.58 13319.89,14979.14 13323,14979.14 C180.1@13336.7,14992.84
HO1: R73.2 U8.8 | length 744.6
  SIG04 w6.5: 13073.63,14896.03 13090,14912.4 13090,15315 13185.86,15410.86 13185.86,15434.14 13135,15485 v2(13135,15545)
  BOTTOM w8: v2(13062.77,14890.12) 13062.77,14886.33 13068.67,14880.42 U8.8@13068.67,14864.53
HO2: R74.1 U8.17 | length 734
  SIG04 w6.5: v2(13190,15545) 13245,15490 13245,14915.18 v2(13257.64,14902.54)
  BOTTOM w6.5: v2(13190,15545) 13190,15521.25 R74.1@13191.25,15520 ; U8.17@13257.65,14864.53 v2(13257.64,14902.54)
I2C_SCL: J15.18 R157.1 | length 1137.1
  SIG04 w6.5: v2(16004.53,16560.61) 16004.63,16560.52 16004.63,16543.94 16023.21,16525.35 16069.65,16525.35 16253.16,16341.84 16521.56,16341.84 16715.91,16147.5 16854.48,16147.5 16876.46,16169.48 v2(16903.3,16169.48)
  BOTTOM w6.5: J15.18@16004.25,16608.92 16004.39,16608.78 16004.39,16560.76 v2(16004.53,16560.61)
I2C_SDA: J15.20 R158.1 | length 1016
  SIG04 w6.5: v2(16035,16560) 16060,16560 16254,16366 16520.74,16366 16717.24,16169.5 v2(16840,16169.5)
  BOTTOM w6.5: v2(16035,16560) 16035.37,16560.37 16035.37,16608.55 J15.20@16035.74,16608.92
ILIM/IMON: R116.2 R118.2 U8.31 | length 375.2
  BOTTOM w6.5: U8.31@13113.95,14701.14 13113.95,14683.95 13055.15,14625.15 13043.25,14625.15 13038.88,14620.78 v2(13035.63,14620.78) 13035.63,14580.51 13065.33,14550.81 13065.33,14479.67 13086.5,14458.5 13114.66,14430.34 R118.2@13145,14430.34
Input_voltage_sense: R62.2 R63.1 R66.1 | length 7184.3
  SIG04 w6.5: v1(12130,16560) 12200,16630 13635,16630 13775,16770 14375,16770 14534,16611 15686,16611 15718,16643 17122,16643 17309,16456 17309,16270.53 17514.53,16065 17670,16065 17710,16105 18205,16105 18310,16000 v2(18310,15830)
  BOTTOM w6.5: R63.1@12090,16515 12090,16558.98 ; R62.2@12090,16588.5 12090,16558.98 ; v1(12130,16560) 12091.02,16560 12090,16558.98 ; R66.1@18303.11,15973.3 18310,15966.41 v2(18310,15830)
L1: L19.2 R77.1 R87.2 | length 712.9
  TOP w6.5: v1(12469.16,14538.45) 12469.16,14617.83 R77.1@12469.31,14617.99
  BOTTOM w6.5: v1(12469.16,14538.45) 12469.16,14689.16 12641.07,14861.07 12879.41,14861.07 R87.2@12880.18,14860.31
L2: L20.1 R78.2 R90.2 | length 640.1
  TOP w6.5: v2(13909.26,14537.74) 13909.26,14614.5 R78.2@13910,14615.24
  BOTTOM w6.5: R90.2@13441.24,14765.39 13519.61,14765.39 13575,14710 13737.01,14710 v2(13909.26,14537.74)
LO1: R84.1 U8.11 | length 459.4
  BOTTOM w6.5: R84.1@12855,15120 12855,15070 12875,15050 13070,15050 13085.88,15034.12 13085.88,14974.46 ; 13085.74,14974.33 13133.63,14926.44 U8.11@13133.63,14890.12
LO2: R85.2 U8.14 | length 291.9
  BOTTOM w6.5: U8.14@13192.69,14890.12 13192.69,14931.77 13244.27,14983.36 13244.27,15059.27 13300,15115 R85.2@13322.57,15115
MCASPX_ACLKX: J15.37 U11.1 | length 172
  TOP w6.5: U11.1@16270,16215 16270,16265 v2(16320,16315)
  BOTTOM w6.5: J15.37@16319.21,16366 16319.6,16365.61 16319.6,16315.4 v2(16320,16315)
MCASPX_AX0: J15.27 U13.1 | length 531.2
  TOP w6.5: v2(16569.29,16262.29) 16570.53,16261.05 16570.53,16216.24 U13.1@16571.77,16215
  SIG03 w6.5: v2(16160,16315) 16212,16263 16568.59,16263 v2(16569.29,16262.29)
  BOTTOM w6.5: v2(16160,16315) 16160.86,16315.86 16160.86,16365.14 J15.27@16161.73,16366
MCASPX_AX1: J15.29 U14.1 | length 645.6
  TOP w6.5: v2(16713,16265) 16713,16261.75 16719.53,16255.23 16719.53,16218.03 U14.1@16723.39,16214.17
  SIG03 w6.5: v2(16195,16315) 16225,16285 16693,16285 v2(16713,16265)
  BOTTOM w6.5: J15.29@16193.22,16366 16194.11,16365.11 16194.11,16315.89 v2(16195,16315)
MCASPX_FSX: J15.39 U12.1 | length 190.9
  TOP w6.5: v2(16400,16315) 16421.77,16293.23 U12.1@16421.77,16215
  BOTTOM w6.5: J15.39@16350.7,16366 16350.7,16346.52 16379.92,16317.3 16397.7,16317.3 v2(16400,16315)
MODE: R114.2 R115.1 R144.2 U8.29 | length 10227.8
  TOP w6.5: v2(13150.52,14620.75) 13150.52,14586.61 R114.2@13150.63,14586.5
  SIG04 w6.5: v2(13150.52,14620.75) 13122.77,14648.5 13100.84,14648.5 12637.84,15111.5 11900.17,15111.5 11773.5,15238.17 11773.5,16896.83 11869.67,16993 18122,16993 v2(18165,16950)
  BOTTOM w6.5: R115.1@13150.63,14586.5 13150.52,14586.61 v2(13150.52,14620.75) 13138.39,14632.87 13138.39,14645.64 13153.32,14660.56 U8.29@13153.32,14694.33 ; v2(18165,16950) 18300,16950 18418.74,16831.26 R144.2@18418.74,16800.39
NETC1_2: C1.2 TP1.1 U1.16 | length 192.3
  TOP w6.5: v2(15380,15690) 15421.5,15690 C1.2@15425,15693.5 15425,15692.52 15446.3,15671.22 U1.16@15446.3,15598.78
  BOTTOM w6.5: v2(15380,15690) 15380.28,15690.28 15421.77,15690.28 TP1.1@15422.05,15690.55
NETC5_1: C5.1 C12.1 U1.3 U1.63 | length 347.8
  TOP w6.5: C5.1@15848.5,15675 15855.75,15667.76 U1.3@15855.75,15598.78 15861.58,15592.95 15861.58,15563.42 15924.65,15500.35 U1.63@15985.67,15500.35 16061.85,15500.35 C12.1@16065,15503.5
NETC5_2: C5.2 U1.2 | length 86.8
  TOP w6.5: U1.2@15887.24,15598.78 15887.24,15651.73 15910.51,15675 C5.2@15911.5,15675
NETC8_1: C8.1 U1.19 | length 179.4
  TOP w6.5: U1.19@15379.37,15468.86 15381.2,15467.03 15417.97,15467.03 15460,15425 v2(15460,15423)
  BOTTOM w6.5: v2@15458.75,15423 v2(15460,15423) 15485,15448 C8.1@15485,15490
NETC9_2: C9.2 U1.14 | length 95
  TOP w6.5: U1.14@15509.29,15598.78 15509.29,15692.8 C9.2@15510,15693.5
NETC12_2: C12.2 U1.64 | length 94.3
  TOP w6.5: U1.64@15985.67,15531.85 16031.34,15531.85 16065,15565.51 C12.2@16065,15566.5
NETC13_1: C13.1 C14.1 L1.2 TP3.1 U1.21 | length 395.6
  TOP w6.5: L1.2@15115,15463.5 15115,15462.52 15128.7,15448.82 15129.69,15448.82 15149.38,15429.12 15180.04,15429.12 C13.1@15200.63,15408.53 ; TP3.1@15125,15405 15197.1,15405 C13.1@15200.63,15408.53 ; U1.21@15379.37,15405.87 15373.54,15411.69 15333.31,15411.69 15332.79,15412.21 15310.19,15412.21 15304.33,15418.06 15304.33,15425.44 C14.1@15290.63,15439.14 15256.93,15439.14 15246.91,15429.12 15221.22,15429.12 C13.1@15200.63,15408.53
NETC19_1: C19.1 TP5.1 U1.30 | length 202.7
  TOP w6.5: U1.30@15379.37,15122.4 15384.93,15127.96 15423.9,15127.96 15440.94,15145 v1(15445,15145)
  BOTTOM w6.5: C19.1@15380,15131.5 15427.44,15131.5 15440.94,15145 v1(15445,15145) 15447.5,15147.5 15497.5,15147.5 TP5.1@15500,15150
NETC19_2: C19.2 L2.4 TP7.1 U1.31 | length 156.7
  BOTTOM w6.5: C19.2@15380,15068.5 15383.5,15065 v1(15447,15065) ; v1(15480,15098) 15523,15098 TP7.1@15555,15130
  other v1: 15577.91,13922.09 15617.28,13922.09 15577.91,13961.46 15617.28,13961.46 15577.91,14000.83 15617.28,14000.83 15480,15065 15447,15098
NETC20_1: C20.1 R1.1 TP4.1 U1.59 | length 229.6
  TOP w6.5: v2(15940,15375) 15940.31,15374.69 15985.35,15374.69 U1.59@15985.67,15374.37 15991.5,15380.2 16026.14,15380.2 16030.94,15385 C20.1@16055,15385
  BOTTOM w6.5: TP4.1@15895,15345 15902.95,15345 15912.47,15354.53 15914.53,15354.53 15929.12,15369.12 15930.87,15369.12 15936.75,15375 15963.91,15375 15967.96,15379.05 15981.16,15379.05 R1.1@15987.97,15385.87
NETC21_1: C21.1 R3.2 TP6.1 U1.60 | length 303.1
  TOP w6.5: v2(15940,15410) 15942.07,15407.93 15983.6,15407.93 U1.60@15985.67,15405.87 16038.36,15405.87 16054.3,15421.8 C21.1@16055.08,15421.8
  BOTTOM w6.5: TP6.1@15835,15390 15842.95,15390 15852.95,15380 15910,15380 v2(15940,15410) 15942.3,15412.3 15961.11,15412.3 15983.82,15435 R3.2@15987.76,15435
NETC22_1: C22.1 L2.1 TP9.1 U1.25 | length 138
  BOTTOM w6.5: C22.1@15380,15296.5 15391.5,15285 v1(15445,15285) ; v1(15480,15285) 15500,15305 TP9.1@15540,15305
  other v1: 15027.91,13922.09 15067.28,13922.09 15027.91,13961.46 15067.28,13961.46 15027.91,14000.83 15067.28,14000.83 15445,15325 15480,15325
NETC22_2: C22.2 TP11.1 U1.26 | length 192.1
  TOP w6.5: U1.26@15379.37,15248.39 15422.56,15248.39 15430.94,15240 v1(15435,15240)
  BOTTOM w6.5: C22.2@15380,15233.5 15424.44,15233.5 15430.94,15240 v1(15435,15240) 15484.65,15240 15486.3,15238.35 TP11.1@15487.7,15238.35 ; 15467.7,15238.35 15477.55,15228.5 TP11.1@15485.5,15228.5
NETC25_1: C25.1 L2.3 R2.1
  other v1: 15620.63,13635 15660,13635 15620.63,13674.37 15660,13674.37 15620.63,13713.74 15660,13713.74
NETC26_1: C26.1 L2.2 R4.1
  other v1: 14975.63,13641.26 15015,13641.26 14975.63,13680.63 15015,13680.63 14975.63,13720 15015,13720
NETC29_1: C29.1 TP12.1 U1.38 | length 213.6
  TOP w6.5: v1(15575,15060) 15597.95,15037.05 15597.95,14998.31 U1.38@15603.78,14992.48
  BOTTOM w6.5: v1(15575,15060) 15575,15003.5 C29.1@15588.5,14990 15580,14981.5 TP12.1@15580,14935
NETC29_2: C29.2 L3.4 TP13.1 U1.39 | length 145.7
  BOTTOM w6.5: v1(15625,15065) 15627.09,15062.91 15627.09,15048.2 15651.5,15023.79 C29.2@15651.5,14990 15640,14978.5 TP13.1@15640,14935
  other v1: 15577.38,14559.16 15616.75,14559.16 15577.38,14598.53 15616.75,14598.53 15577.38,14637.9 15616.75,14637.9 15653.52,15064.92 15625,15095 15655,15095
NETC30_1: C30.1 L3.1 TP15.1 U1.34 | length 316.6
  TOP w6.5: TP15.1@15035,14590 15162.13,14590 L3.1@15167.2,14595.07
  BOTTOM w6.5: v1(15395,14845) 15458.5,14908.5 C30.1@15458.5,15000 C30.1@15459.49,15000
NETC30_2: C30.2 TP17.1 U1.35 | length 281.1
  TOP w6.5: U1.35@15509.29,14992.48 15515.12,14998.31 15511.07,15002.36 15511.07,15040.04 15530,15058.98 v1(15530,15060)
  BOTTOM w6.5: C30.2@15530,14991.5 C30.2@15521.5,15000 15530,15008.5 v1(15530,15060) 15599.26,15129.26 15599.26,15134.46 15599.38,15134.57 15599.38,15149.38 TP17.1@15605,15155
NETC33_1: C33.1 L3.3 R8.1
  other v1: 15580,14361.26 15619.37,14361.26 15580,14400.63 15619.37,14400.63 15580,14440 15619.37,14440
NETC34_1: C34.1 L3.2 R10.1
  other v1: 15020,14276.26 15059.37,14276.26 15020,14315.63 15059.37,14315.63 15020,14355 15059.37,14355
NETC37_1: C37.1 TP18.1 U1.46 | length 285
  TOP w6.5: v1(15840,15055) 15840,15051.55 15849.91,15041.64 15849.91,15025.09 15849.92,14998.31 U1.46@15855.75,14992.48
  BOTTOM w6.5: TP18.1@15805,15190 15805,15138.06 15840,15103.06 v1(15840,15055) 15840,14993.5 C37.1@15843.5,14990
NETC37_2: C37.2 L4.4 TP19.1 U1.47 | length 151
  BOTTOM w6.5: C37.2@15906.5,14990 15907.48,14990 15980,14917.48 v1(15980,14915) TP19.1@15980,14870
NETC38_1: C38.1 L4.1 TP21.1 U1.42 | length 165.5
  BOTTOM w6.5: C38.1@15713.5,14990 15715,14991.5 v1(15715,15065) ; v1(15750,14638.74) 15798.95,14638.74 15822.69,14615 TP21.1@15830,14615
  other v1: 15710.63,14560 15750,14560 15710.63,14599.37 15750,14599.37 15710.63,14638.74 15747.09,15063.01 15715,15098 15747.09,15098.01
NETC38_2: C38.2 TP23.1 U1.43 | length 312
  TOP w6.5: U1.43@15761.26,14992.48 15767.09,14998.31 15767.09,15019.02 15770.93,15022.87 15770.93,15025.42 15778.51,15033.01 15783.01,15033.01 v1(15805,15055)
  BOTTOM w6.5: TP23.1@15740,15180 15745.24,15174.76 15745.24,15145.31 15803.06,15087.5 15803.06,15056.94 v1(15805,15055) 15776.5,15026.5 C38.2@15776.5,14990
NETC41_1: C41.1 L4.3 R12.1
  other v1: 16235,14361.26 16274.37,14361.26 16235,14400.63 16274.37,14400.63 16235,14440 16274.37,14440
NETC42_1: C42.1 L4.2 R13.1
  other v1: 15705.63,14360 15745,14360 15705.63,14399.37 15745,14399.37 15705.63,14438.74 15745,14438.74
NETC45_1: C45.1 TP24.1 U1.55 | length 241.1
  TOP w6.5: v1(15910,15215) 15912.87,15217.87 15922.87,15217.87 15947.56,15242.56 15979.84,15242.56 U1.55@15985.67,15248.39
  BOTTOM w6.5: TP24.1@15849,15230 15853.03,15225.97 15874.03,15225.97 15885,15215 15940,15215 15949.6,15224.6 15970.04,15224.6 15983.74,15238.3 C45.1@15983.74,15239.28
NETC45_2: C45.2 L5.4 TP25.1 U1.56 | length 109.4
  BOTTOM w6.5: TP25.1@15842,15305 15842.52,15304.48 15880.2,15304.48 v1(15880.73,15303.96) ; v1(15914.23,15304.03) 15981.99,15304.03 C45.2@15983.74,15302.28
  other v1: 16262.91,13922.09 16302.28,13922.09 16262.91,13961.46 16302.28,13961.46 16262.91,14000.83 16302.28,14000.83 15880.83,15267.76 15913.73,15267.76
NETC46_1: C46.1 L5.1 TP27.1 U1.50 | length 126.8
  BOTTOM w6.5: v1(15918,15077) 15982.5,15077 C46.1@15984,15078.5 15984.5,15078 TP27.1@16044,15078
  other v1: 15950.63,13911.26 15990,13911.26 15950.63,13955.63 15990,13955.63 15950.63,14000 15990,14000 15885,15077 15885,15110 15918,15110
NETC46_2: C46.2 TP29.1 U1.51 | length 221.8
  TOP w6.5: v1(15915,15165) 15951.77,15128.23 15979.84,15128.23 U1.51@15985.67,15122.4
  BOTTOM w6.5: TP29.1@15865,15175 15872.95,15175 15882.95,15165 v1(15915,15165) 15960.5,15165 15969.31,15156.18 15970.3,15156.18 15984,15142.48 C46.2@15984,15141.5
NETC49_1: C49.1 L5.3 R14.1
  other v1: 16175,13590 16214.37,13590 16175,13629.37 16214.37,13629.37 16175,13668.74 16214.37,13668.74
NETC50_1: C50.1 L5.2 R17.1
  other v1: 15765.63,13590 15805,13590 15765.63,13629.37 15805,13629.37 15765.63,13668.74 15805,13668.74
NETC53_2: C53.2 TP31.1 U2.16 | length 147.1
  TOP w6.5: TP31.1@17065,15670 C53.2@17130,15670 17130,15635.31 17142.01,15623.31 17145.47,15623.31 17151.3,15617.48 U2.16@17151.3,15598.78
NETC57_1: C57.1 C64.1 U2.3 U2.63 | length 371.4
  TOP w6.5: C57.1@17543.5,15685 17543.5,15651.3 17554.92,15639.88 17554.92,15604.61 U2.3@17560.75,15598.78 17566.58,15592.95 17566.58,15558.42 17624.65,15500.35 U2.63@17690.67,15500.35 17768.15,15500.35 C64.1@17775,15493.5
NETC57_2: C57.2 U2.2 | length 92.4
  TOP w6.5: U2.2@17592.24,15598.78 17592.24,15671.3 17605.95,15685 C57.2@17606.5,15685
NETC60_1: C60.1 U2.19 | length 135.2
  TOP w6.5: U2.19@17084.37,15468.86 17084.94,15469.43 17128.9,15469.43 17137.7,15460.62 17137.7,15452.3 v2(17140,15450)
  BOTTOM w6.5: C60.1@17084.37,15476.1 17104.37,15456.1 17130.65,15456.1 17136.75,15450 v2(17140,15450)
NETC61_2: C61.2 U2.14 | length 72.5
  TOP w6.5: U2.14@17214.29,15598.78 17214.29,15664.7 C61.2@17218.97,15669.38
NETC64_2: C64.2 U2.64 | length 94.5
  TOP w6.5: U2.64@17690.67,15531.85 17709.37,15531.85 17734.02,15556.5 C64.2@17775,15556.5
NETC65_1: C65.1 C66.1 L6.2 TP32.1 U2.21 | length 328.5
  TOP w6.5: TP32.1@16835,15505 16835,15446.5 L6.2@16836.5,15445 16843.58,15437.91 C65.1@16910,15437.91 16914.61,15442.52 17005,15442.52 17041.65,15405.87 U2.21@17084.37,15405.87
NETC71_1: C71.1 TP34.1 U2.30 | length 226
  TOP w6.5: U2.30@17084.37,15122.4 17086.97,15125 17115,15125 v1(17150,15160)
  BOTTOM w6.5: C71.1@17085,15136.5 17085,15137.48 17098.7,15151.18 17099.69,15151.18 17108.5,15160 v1(17150,15160) ; v1@17150.89,15160 17191.96,15160 17210.96,15141 TP34.1@17212.5,15141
